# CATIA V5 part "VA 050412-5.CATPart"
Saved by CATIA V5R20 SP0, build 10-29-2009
Part number: VA 050412-5
Revision: ANY
Definition: UNKNOWN
Nomenclature: VA 050412-5
Source: Unknown
Bounding box of the stored display mesh (mm): x -1.25 to 1.25, y -0.25 to 0.25, z -1.25 to 1.25
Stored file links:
  C:\Users\Utente\Desktop\IO LAVORO\3D X SITO CF\CUMSA\3D files VA\VA 050412\VA 050412-5.CATPart
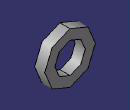
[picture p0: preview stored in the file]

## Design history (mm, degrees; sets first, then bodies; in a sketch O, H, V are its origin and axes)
Body1 "Revolución1" (main body)
  Solid1: solid without history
